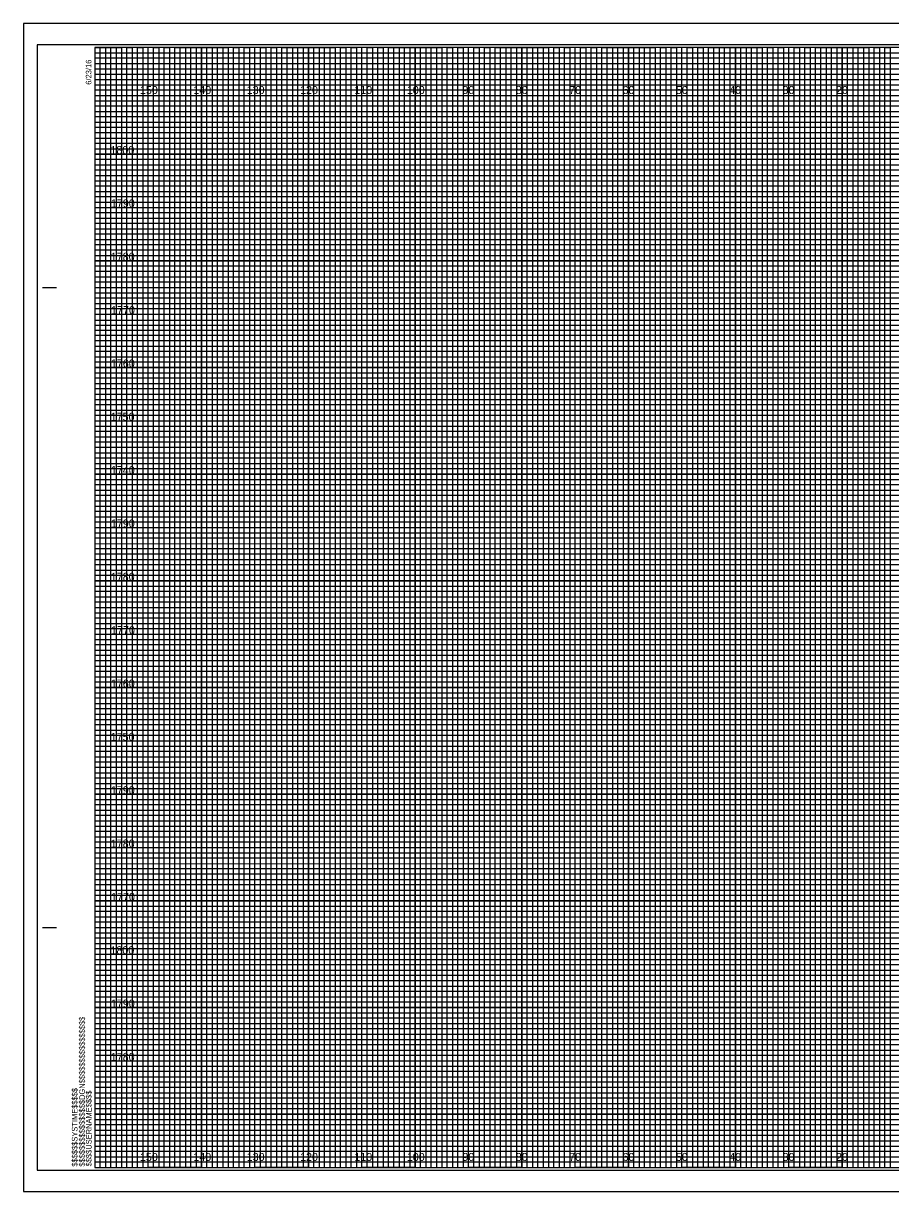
# Model space of a CAD drawing. Extents: x -163 to 174, y 11 to 1110.
# Drawn here: x -162.9 to -0.4, y 451.2 to 670.2 of the extents above; entities that cross this region are included whole.
import ezdxf

# ---------------------------------------------------------------- set-up
doc = ezdxf.new("R2010")
doc.units = 0
for name, color, linetype in [('Prop XS DDE', 7, 'Continuous'), ('Prop XS Earthwork Shape', 7, 'Continuous'), ('Prop XS Elevation Labels', 7, 'Continuous'), ('Sheet Cross Section CELL', 7, 'Continuous'), ('Sheet Cross Section Grid Middle CELL', 7, 'Continuous'), ('Sheet Cross Section Grid Minor 1 CELL', 7, 'Continuous'), ('Sheet Cross Section Grid Minor 2 CELL', 7, 'Continuous'), ('Sheet Cutting Line CELL', 7, 'Continuous'), ('Sheet DOT Grid CELL', 7, 'Continuous'), ('Sheet Plot Border Inside CELL', 7, 'Continuous'), ('Sheet Plot Border Outside CELL', 7, 'Continuous')]:
    doc.layers.add(name, color=color, linetype=linetype)

msp = doc.modelspace()

# ---------------------------------------------------------------- linework, layer by layer
at = {"layer": 'Prop XS DDE'}
for p, q in [((-139.53, 665.7), (-149.53, 665.7)), ((-139.53, 455.7), (-139.53, 665.7)), ((-119.53, 665.7), (-129.53, 665.7)), ((-129.53, 665.7), (-129.53, 455.7)), ((-119.53, 455.7), (-119.53, 665.7)), ((-99.53, 665.7), (-109.53, 665.7)), ((-109.53, 665.7), (-109.53, 455.7)), ((-99.53, 455.7), (-99.53, 665.7)), ((-79.53, 665.7), (-89.53, 665.7)), ((-89.53, 665.7), (-89.53, 455.7)), ((-79.53, 455.7), (-79.53, 665.7)), ((-59.53, 665.7), (-69.53, 665.7)), ((-69.53, 665.7), (-69.53, 455.7)), ((-59.53, 455.7), (-59.53, 665.7)), ((-39.53, 665.7), (-49.53, 665.7)), ((-49.53, 665.7), (-49.53, 455.7)), ((-39.53, 455.7), (-39.53, 665.7)), ((-19.53, 665.7), (-29.53, 665.7)), ((-29.53, 665.7), (-29.53, 455.7)), ((-19.53, 455.7), (-19.53, 665.7)), ((0.47, 665.7), (-9.53, 665.7)), ((-9.53, 665.7), (-9.53, 455.7)), ((-129.53, 455.7), (-139.53, 455.7)), ((-109.53, 455.7), (-119.53, 455.7)), ((-89.53, 455.7), (-99.53, 455.7)), ((-69.53, 455.7), (-79.53, 455.7)), ((-49.53, 455.7), (-59.53, 455.7)), ((-29.53, 455.7), (-39.53, 455.7)), ((-9.53, 455.7), (-19.53, 455.7))]:
    msp.add_line(p, q, dxfattribs=at)
for points in [[(-149.53, 655.7), (170.47, 655.7), (170.47, 645.7), (-149.53, 645.7)], [(-149.53, 635.7), (170.47, 635.7), (170.47, 625.7), (-149.53, 625.7)], [(-149.53, 615.7), (170.47, 615.7), (170.47, 605.7), (-149.53, 605.7)], [(-149.53, 595.7), (170.47, 595.7), (170.47, 585.7), (-149.53, 585.7)], [(-149.53, 575.7), (170.47, 575.7), (170.47, 565.7), (-149.53, 565.7)], [(-149.53, 555.7), (170.47, 555.7), (170.47, 545.7), (-149.53, 545.7)], [(-149.53, 535.7), (170.47, 535.7), (170.47, 525.7), (-149.53, 525.7)], [(-149.53, 515.7), (170.47, 515.7), (170.47, 505.7), (-149.53, 505.7)], [(-149.53, 495.7), (170.47, 495.7), (170.47, 485.7), (-149.53, 485.7)], [(-149.53, 475.7), (170.47, 475.7), (170.47, 465.7), (-149.53, 465.7)]]:
    msp.add_lwpolyline(points, dxfattribs=at)
at = {"layer": 'Sheet Cross Section CELL'}
for p, q in [((-159.33, 620.7), (-156.83, 620.7)), ((-159.23, 620.7), (-156.73, 620.7)), ((-159.33, 500.7), (-156.83, 500.7)), ((-159.23, 500.7), (-156.73, 500.7)), ((-149.53, 455.7), (-149.53, 455.7)), ((-149.53, 455.7), (-149.53, 455.7)), ((-149.53, 455.7), (-149.53, 455.7)), ((-149.53, 455.7), (-149.53, 455.7)), ((-149.53, 455.7), (-149.53, 455.7)), ((-149.53, 455.7), (-149.53, 455.7)), ((-149.53, 455.7), (-149.53, 455.7))]:
    msp.add_line(p, q, dxfattribs=at)
msp.add_lwpolyline([(170.47, 665.7), (-149.53, 665.7), (-149.53, 455.7), (170.47, 455.7)], close=True, dxfattribs=at)
at = {"layer": 'Sheet Cross Section Grid Middle CELL'}
for points in [[(-149.53, 665.7), (-144.53, 665.7), (-144.53, 455.7), (-134.53, 455.7), (-134.53, 665.7), (-124.53, 665.7), (-124.53, 455.7), (-114.53, 455.7), (-114.53, 665.7), (-104.53, 665.7), (-104.53, 455.7), (-94.53, 455.7), (-94.53, 665.7), (-84.53, 665.7), (-84.53, 455.7), (-74.53, 455.7), (-74.53, 665.7), (-64.53, 665.7), (-64.53, 455.7), (-54.53, 455.7), (-54.53, 665.7), (-44.53, 665.7), (-44.53, 455.7), (-34.53, 455.7), (-34.53, 665.7), (-24.53, 665.7), (-24.53, 455.7), (-14.53, 455.7), (-14.53, 665.7), (-4.53, 665.7), (-4.53, 455.7), (5.47, 455.7)], [(-149.53, 660.7), (125.47, 660.7)], [(-149.53, 640.7), (170.47, 640.7), (170.47, 650.7), (-149.53, 650.7)], [(-149.53, 620.7), (170.47, 620.7), (170.47, 630.7), (-149.53, 630.7)], [(-149.53, 600.7), (170.47, 600.7), (170.47, 610.7), (-149.53, 610.7)], [(-149.53, 580.7), (170.47, 580.7), (170.47, 590.7), (-149.53, 590.7)], [(-149.53, 560.7), (170.47, 560.7), (170.47, 570.7), (-149.53, 570.7)], [(-149.53, 540.7), (170.47, 540.7), (170.47, 550.7), (-149.53, 550.7)], [(-149.53, 520.7), (170.47, 520.7), (170.47, 530.7), (-149.53, 530.7)], [(-149.53, 500.7), (170.47, 500.7), (170.47, 510.7), (-149.53, 510.7)], [(-149.53, 480.7), (170.47, 480.7), (170.47, 490.7), (-149.53, 490.7)], [(-149.53, 460.7), (170.47, 460.7), (170.47, 470.7), (-149.53, 470.7)]]:
    msp.add_lwpolyline(points, dxfattribs=at)
at = {"layer": 'Sheet Cross Section Grid Minor 1 CELL'}
for p, q in [((-149.53, 664.7), (110.47, 664.7)), ((110.47, 663.68), (-149.53, 663.68)), ((-149.53, 663.68), (-149.53, 662.7)), ((-149.53, 662.7), (110.47, 662.7)), ((110.47, 661.59), (-149.53, 661.59)), ((-149.53, 661.59), (-149.53, 659.7)), ((-149.53, 659.7), (170.47, 659.7))]:
    msp.add_line(p, q, dxfattribs=at)
for points in [[(-149.53, 658.7), (120.47, 658.7), (170.47, 658.7), (170.47, 657.7), (-149.53, 657.7)], [(-149.53, 656.7), (170.47, 656.7), (170.47, 654.7), (-149.53, 654.7)], [(-149.53, 653.7), (170.47, 653.7), (170.47, 652.7), (-149.53, 652.68)], [(-149.53, 651.7), (170.47, 651.7), (170.47, 649.7), (-149.53, 649.7)], [(-149.53, 648.7), (170.47, 648.7), (170.47, 647.7), (-149.53, 647.7)], [(-149.53, 646.7), (170.47, 646.7), (170.47, 644.7), (-149.53, 644.7)], [(-149.53, 643.7), (170.47, 643.7), (170.47, 642.7), (-149.53, 642.7)], [(-149.53, 641.7), (170.47, 641.7), (170.47, 639.7), (-149.53, 639.7)], [(-149.53, 638.7), (170.47, 638.7), (170.47, 637.7), (-149.53, 637.7)], [(-149.53, 636.7), (170.47, 636.7), (170.47, 634.7), (-149.53, 634.7)], [(-149.53, 633.7), (170.47, 633.7), (170.47, 632.7), (-149.53, 632.7)], [(-149.53, 631.7), (170.47, 631.7), (170.47, 629.65), (170.47, 628.7), (170.47, 627.7), (-149.53, 627.7)], [(-149.53, 629.7), (170.47, 629.7), (170.47, 628.7), (-149.53, 628.7)], [(-149.53, 626.7), (170.47, 626.7), (170.47, 624.7), (-149.53, 624.73)], [(-149.53, 624.73), (170.47, 624.7), (170.47, 623.7), (-149.53, 623.7)], [(-149.53, 622.7), (170.47, 622.7), (170.47, 621.7), (-149.53, 621.7)], [(-149.53, 619.7), (170.47, 619.7), (170.47, 618.7), (-149.53, 618.7)], [(-149.53, 617.7), (170.47, 617.7), (170.47, 616.7), (-149.53, 616.7)], [(-149.6, 614.59), (170.47, 614.59), (170.47, 613.58), (-149.6, 613.58)], [(-149.53, 612.7), (170.47, 612.7), (170.47, 611.7), (-149.53, 611.7)], [(-149.53, 609.7), (170.47, 609.7), (170.47, 608.7), (-149.53, 608.7)], [(-149.53, 607.7), (170.47, 607.7), (170.47, 606.7), (-149.53, 606.7)], [(-149.53, 604.7), (170.47, 604.7), (170.47, 603.7), (-149.53, 603.7)], [(-149.53, 602.7), (170.47, 602.7), (170.47, 601.7), (-149.53, 601.7)], [(-149.53, 599.7), (170.47, 599.7), (170.47, 598.7), (-149.53, 598.7)], [(-149.53, 597.7), (170.47, 597.7), (170.47, 596.7), (-149.53, 596.7)], [(-149.53, 594.7), (170.47, 594.7), (170.46, 593.68), (-149.53, 593.7)], [(-149.53, 592.7), (170.47, 592.7), (170.47, 591.7), (-149.53, 591.7)], [(-149.53, 589.7), (170.47, 589.7), (170.47, 588.7), (-149.53, 588.7)], [(-149.53, 587.7), (170.47, 587.7), (170.47, 586.7), (-149.53, 586.7)], [(-149.53, 584.7), (170.47, 584.7), (170.47, 583.7), (-149.53, 583.7)], [(-149.53, 582.7), (170.47, 582.7), (170.47, 581.7), (-149.53, 581.7)], [(-149.53, 579.7), (170.47, 579.7), (170.47, 578.7), (-149.53, 578.7)], [(-149.53, 577.7), (170.47, 577.7), (170.47, 576.7), (-149.53, 576.7)], [(-149.53, 574.7), (170.47, 574.7), (170.47, 573.7), (-149.53, 573.7)], [(-149.53, 572.69), (170.54, 572.61), (170.47, 571.7), (-149.53, 571.7)], [(-149.53, 569.7), (170.47, 569.7), (170.47, 568.7), (-149.53, 568.7)], [(-149.53, 567.7), (170.47, 567.7), (170.47, 566.7), (-149.53, 566.7)], [(-149.53, 564.7), (170.47, 564.7), (170.47, 563.7), (-149.53, 563.7)], [(-149.53, 562.7), (170.47, 562.7), (170.47, 561.7), (-149.53, 561.7)], [(-149.53, 559.7), (170.47, 559.7), (170.47, 558.7), (-149.53, 558.7)], [(-149.53, 557.7), (170.47, 557.7), (170.47, 556.7), (-149.53, 556.7)], [(-149.53, 554.7), (170.47, 554.7), (170.47, 553.7), (-149.53, 553.7)], [(-149.53, 552.7), (170.47, 552.7), (170.47, 551.7), (-149.53, 551.7)], [(-149.53, 549.7), (170.47, 549.7), (170.47, 548.7), (-149.53, 548.7)], [(-149.53, 547.7), (170.47, 547.7), (170.47, 546.7), (-149.53, 546.7)], [(-149.53, 544.7), (170.47, 544.7), (170.47, 543.7), (-149.53, 543.7)], [(-149.53, 542.7), (170.47, 542.7), (170.47, 541.7), (-149.53, 541.7)], [(-149.53, 539.7), (170.47, 539.7), (170.47, 538.7), (-149.53, 538.7)], [(-149.53, 537.7), (170.47, 537.7), (170.47, 536.7), (-149.53, 536.7)], [(-149.53, 534.7), (170.47, 534.7), (170.46, 533.68), (-149.53, 533.7)], [(-149.53, 532.7), (170.47, 532.7), (170.47, 531.7), (-149.53, 531.7)], [(-149.53, 529.7), (170.47, 529.7), (170.47, 528.7), (-149.53, 528.7)], [(-149.53, 527.7), (170.47, 527.7), (170.47, 526.7), (-149.53, 526.7)], [(-149.53, 524.7), (170.47, 524.7), (170.47, 523.7), (-149.53, 523.7)], [(-149.53, 522.7), (170.47, 522.7), (170.47, 521.7), (-149.53, 521.7)], [(-149.53, 519.7), (170.47, 519.7), (170.47, 518.7), (-149.53, 518.7)], [(-149.53, 517.7), (170.47, 517.7), (170.47, 516.7), (-149.53, 516.7)], [(-149.53, 514.7), (170.47, 514.7), (170.47, 513.7), (-149.53, 513.7)], [(-149.53, 512.69), (170.54, 512.61), (170.47, 511.7), (-149.53, 511.7)], [(-149.53, 509.7), (170.47, 509.7), (170.47, 508.7), (-149.53, 508.7)], [(-149.53, 507.7), (170.47, 507.7), (170.47, 506.7), (-149.53, 506.7)], [(-149.53, 504.7), (170.47, 504.7), (170.47, 503.7), (-149.53, 503.7)], [(-149.53, 502.7), (170.47, 502.7), (170.47, 501.7), (-149.53, 501.7)], [(-149.53, 499.7), (170.47, 499.7), (170.47, 498.7), (-149.53, 498.7)], [(-149.53, 497.7), (170.47, 497.7), (170.47, 496.7), (-149.53, 496.7)], [(-149.53, 494.7), (170.47, 494.7), (170.47, 493.7), (-149.53, 493.7)], [(-149.53, 492.7), (170.47, 492.7), (170.47, 491.7), (-149.53, 491.7)], [(-149.53, 489.7), (170.47, 489.7), (170.47, 488.7), (-149.53, 488.7)], [(-149.53, 487.7), (170.47, 487.7), (170.47, 486.7), (-149.53, 486.7)], [(-149.53, 484.7), (170.47, 484.7), (170.47, 483.7), (-149.53, 483.7)], [(-149.53, 482.7), (170.47, 482.7), (170.47, 481.7), (-149.53, 481.7)], [(-149.53, 479.7), (170.47, 479.7), (170.47, 478.7), (-149.53, 478.7)], [(-149.53, 477.7), (170.47, 477.7), (170.47, 476.7), (-149.53, 476.7)], [(-149.53, 474.7), (170.47, 474.7), (170.47, 473.7), (-149.53, 473.7)], [(-149.53, 472.7), (170.47, 472.7), (170.47, 471.7), (-149.53, 471.7)], [(-149.53, 469.7), (170.47, 469.7), (170.47, 468.7), (-149.53, 468.7)], [(-149.53, 467.7), (170.47, 467.7), (170.47, 466.7), (-149.53, 466.7)], [(-149.53, 464.7), (170.47, 464.7), (170.47, 463.7), (-149.53, 463.7)], [(-149.53, 462.7), (170.47, 462.7), (170.47, 461.7), (-149.53, 461.7)], [(-149.53, 459.7), (170.47, 459.7), (170.47, 458.7), (-149.53, 458.7)], [(-149.53, 457.7), (170.47, 457.7), (170.47, 456.7), (-149.53, 456.7)]]:
    msp.add_lwpolyline(points, dxfattribs=at)
at = {"layer": 'Sheet Cross Section Grid Minor 2 CELL'}
for points in [[(-149.53, 455.7), (-148.53, 455.7), (-148.53, 665.7), (-147.53, 665.7), (-147.53, 455.7)], [(-147.53, 455.7), (-146.53, 455.7), (-146.53, 665.7), (-145.53, 665.7), (-145.53, 455.7)], [(-144.53, 455.7), (-143.53, 455.7), (-143.53, 665.7), (-142.53, 665.7), (-142.53, 455.7)], [(-142.53, 455.7), (-141.53, 455.7), (-141.53, 665.7), (-140.53, 665.7), (-140.53, 455.7)], [(-139.53, 455.7), (-138.53, 455.7), (-138.53, 665.7), (-137.53, 665.7), (-137.53, 455.7)], [(-137.53, 455.7), (-136.53, 455.7), (-136.53, 665.7), (-135.53, 665.7), (-135.53, 455.7)], [(-134.53, 455.7), (-133.53, 455.7), (-133.53, 665.7), (-132.53, 665.7), (-132.53, 455.7)], [(-132.53, 455.7), (-131.53, 455.7), (-131.53, 665.7), (-130.53, 665.7), (-130.53, 455.7)], [(-129.53, 455.7), (-128.53, 455.7), (-128.53, 665.7), (-127.53, 665.7), (-127.53, 455.7)], [(-127.53, 455.7), (-126.53, 455.7), (-126.53, 665.7), (-125.53, 665.7), (-125.53, 455.7)], [(-124.53, 455.7), (-123.53, 455.7), (-123.53, 665.7), (-122.53, 665.7), (-122.53, 455.7)], [(-122.53, 455.7), (-121.53, 455.7), (-121.53, 665.7), (-120.53, 665.7), (-120.53, 455.7)], [(-119.53, 455.7), (-118.53, 455.7), (-118.53, 665.7), (-117.53, 665.7), (-117.53, 455.7)], [(-117.53, 455.7), (-116.53, 455.7), (-116.53, 665.7), (-115.53, 665.7), (-115.53, 455.7)], [(-114.53, 455.7), (-113.53, 455.7), (-113.53, 665.7), (-112.53, 665.7), (-112.53, 455.7)], [(-112.53, 455.7), (-111.53, 455.7), (-111.53, 665.7), (-110.53, 665.7), (-110.53, 455.7)], [(-109.53, 455.7), (-108.53, 455.7), (-108.53, 665.7), (-107.53, 665.7), (-107.53, 455.7)], [(-107.53, 455.7), (-106.53, 455.7), (-106.53, 665.7), (-105.53, 665.7), (-105.53, 455.7)], [(-104.53, 455.7), (-103.53, 455.7), (-103.53, 665.7), (-102.53, 665.7), (-102.53, 455.7)], [(-102.53, 455.7), (-101.53, 455.7), (-101.53, 665.7), (-100.53, 665.7), (-100.53, 455.7)], [(-99.53, 455.7), (-98.53, 455.7), (-98.53, 665.7), (-97.53, 665.7), (-97.53, 455.7)], [(-97.53, 455.7), (-96.53, 455.7), (-96.53, 665.7), (-95.53, 665.7), (-95.53, 455.7)], [(-94.53, 455.7), (-93.53, 455.7), (-93.53, 665.7), (-92.53, 665.7), (-92.53, 455.7)], [(-92.53, 455.7), (-91.53, 455.7), (-91.53, 665.7), (-90.53, 665.7), (-90.53, 455.7)], [(-89.53, 455.7), (-88.53, 455.7), (-88.53, 665.7), (-87.53, 665.7), (-87.53, 455.7)], [(-87.53, 455.7), (-86.53, 455.7), (-86.53, 665.7), (-85.53, 665.7), (-85.53, 455.7)], [(-84.53, 455.7), (-83.53, 455.7), (-83.53, 665.7), (-82.53, 665.7), (-82.53, 455.7)], [(-82.53, 455.7), (-81.53, 455.7), (-81.53, 665.7), (-80.53, 665.7), (-80.53, 455.7)], [(-79.53, 455.7), (-78.53, 455.7), (-78.53, 665.7), (-77.53, 665.7), (-77.53, 455.7)], [(-77.53, 455.7), (-76.53, 455.7), (-76.53, 665.7), (-75.53, 665.7), (-75.53, 455.7)], [(-74.53, 455.7), (-73.53, 455.7), (-73.53, 665.7), (-72.53, 665.7), (-72.53, 455.7)], [(-72.53, 455.7), (-71.53, 455.7), (-71.53, 665.7), (-70.53, 665.7), (-70.53, 455.7)], [(-69.53, 455.7), (-68.53, 455.7), (-68.53, 665.7), (-67.53, 665.7), (-67.53, 455.7)], [(-67.53, 455.7), (-66.53, 455.7), (-66.53, 665.7), (-65.53, 665.7), (-65.53, 455.7)], [(-64.53, 455.7), (-63.53, 455.7), (-63.53, 665.7), (-62.53, 665.7), (-62.53, 455.7)], [(-62.53, 455.7), (-61.53, 455.7), (-61.53, 665.7), (-60.53, 665.7), (-60.53, 455.7)], [(-59.53, 455.7), (-58.53, 455.7), (-58.53, 665.7), (-57.53, 665.7), (-57.53, 455.7)], [(-57.53, 455.7), (-56.53, 455.7), (-56.53, 665.7), (-55.53, 665.7), (-55.53, 455.7)], [(-54.53, 455.7), (-53.53, 455.7), (-53.53, 665.7), (-52.53, 665.7), (-52.53, 455.7)], [(-52.53, 455.7), (-51.53, 455.7), (-51.53, 665.7), (-50.53, 665.7), (-50.53, 455.7)], [(-49.53, 455.7), (-48.53, 455.7), (-48.53, 665.7), (-47.53, 665.7), (-47.53, 455.7)], [(-47.53, 455.7), (-46.53, 455.7), (-46.53, 665.7), (-45.53, 665.7), (-45.53, 455.7)], [(-44.53, 455.7), (-43.53, 455.7), (-43.53, 665.7), (-42.53, 665.7), (-42.53, 455.7)], [(-42.53, 455.7), (-41.53, 455.7), (-41.53, 665.7), (-40.53, 665.7), (-40.53, 455.7)], [(-39.53, 455.7), (-38.53, 455.7), (-38.53, 665.7), (-37.53, 665.7), (-37.53, 455.7)], [(-37.53, 455.7), (-36.53, 455.7), (-36.53, 665.7), (-35.53, 665.7), (-35.53, 455.7)], [(-34.53, 455.7), (-33.53, 455.7), (-33.53, 665.7), (-32.53, 665.7), (-32.53, 455.7)], [(-32.53, 455.7), (-31.53, 455.7), (-31.53, 665.7), (-30.53, 665.7), (-30.53, 455.7)], [(-29.53, 455.7), (-28.53, 455.7), (-28.53, 665.7), (-27.53, 665.7), (-27.53, 455.7)], [(-27.53, 455.7), (-26.53, 455.7), (-26.53, 665.7), (-25.53, 665.7), (-25.53, 455.7)], [(-24.53, 455.7), (-23.53, 455.7), (-23.53, 665.7), (-22.53, 665.7), (-22.53, 455.7)], [(-22.53, 455.7), (-21.53, 455.7), (-21.53, 665.7), (-20.53, 665.7), (-20.53, 455.7)], [(-19.53, 455.7), (-18.53, 455.7), (-18.53, 665.7), (-17.53, 665.7), (-17.53, 455.7)], [(-17.53, 455.7), (-16.53, 455.7), (-16.53, 665.7), (-15.53, 665.7), (-15.53, 455.7)], [(-14.53, 455.7), (-13.53, 455.7), (-13.53, 665.7), (-12.53, 665.7), (-12.53, 455.7)], [(-12.53, 455.7), (-11.53, 455.7), (-11.53, 665.7), (-10.53, 665.7), (-10.53, 455.7)], [(-9.53, 455.7), (-8.53, 455.7), (-8.53, 665.7), (-7.53, 665.7), (-7.53, 455.7)], [(-7.53, 455.7), (-6.53, 455.7), (-6.53, 665.7), (-5.53, 665.7), (-5.53, 455.7)], [(-4.53, 455.7), (-3.53, 455.7), (-3.53, 665.7), (-2.53, 665.7), (-2.53, 455.7)], [(-2.53, 455.7), (-1.53, 455.7), (-1.53, 665.7), (-0.53, 665.7), (-0.53, 455.7)]]:
    msp.add_lwpolyline(points, dxfattribs=at)
at = {"layer": 'Sheet Cutting Line CELL'}
for p, q in [((173.77, 670.2), (-162.93, 670.2)), ((-162.93, 670.2), (-162.93, 451.2)), ((-162.93, 451.2), (173.77, 451.2))]:
    msp.add_line(p, q, dxfattribs=at)
at = {"layer": 'Sheet DOT Grid CELL'}
for p, q in [((-139.53, 455.7), (-139.53, 665.7)), ((-129.53, 455.7), (-129.53, 665.7)), ((-119.53, 455.7), (-119.53, 665.7)), ((-109.53, 455.7), (-109.53, 665.7)), ((-99.53, 455.7), (-99.53, 665.7)), ((-89.53, 455.7), (-89.53, 665.7)), ((-79.53, 455.7), (-79.53, 665.7)), ((-69.53, 455.7), (-69.53, 665.7)), ((-59.53, 455.7), (-59.53, 665.7)), ((-49.53, 455.7), (-49.53, 665.7)), ((-39.53, 455.7), (-39.53, 665.7)), ((-29.53, 455.7), (-29.53, 665.7)), ((-19.53, 455.7), (-19.53, 665.7)), ((-9.53, 455.7), (-9.53, 665.7)), ((-149.53, 655.7), (170.47, 655.7)), ((-149.53, 645.7), (170.47, 645.7)), ((-149.53, 635.7), (170.47, 635.7)), ((-149.53, 625.7), (170.47, 625.7)), ((-149.53, 615.7), (170.47, 615.7)), ((-149.53, 605.7), (170.47, 605.7)), ((-149.53, 595.7), (170.47, 595.7)), ((-149.53, 585.7), (170.47, 585.7)), ((-149.53, 575.7), (170.47, 575.7)), ((-149.53, 565.7), (170.47, 565.7)), ((-149.53, 555.7), (170.47, 555.7)), ((-149.53, 545.7), (170.47, 545.7)), ((-149.53, 535.7), (170.47, 535.7)), ((-149.53, 525.7), (170.47, 525.7)), ((-149.53, 515.7), (170.47, 515.7)), ((-149.53, 505.7), (170.47, 505.7)), ((-149.53, 495.7), (170.47, 495.7)), ((-149.53, 485.7), (170.47, 485.7)), ((-149.53, 475.7), (170.47, 475.7)), ((-149.53, 465.7), (170.47, 465.7))]:
    msp.add_line(p, q, dxfattribs=at)
at = {"layer": 'Sheet Plot Border Inside CELL'}
msp.add_lwpolyline([(-160.33, 455.2), (172.87, 455.2), (172.87, 666.2), (-160.33, 666.2)], close=True, dxfattribs=at)
at = {"layer": 'Sheet Plot Border Outside CELL'}
msp.add_lwpolyline([(-162.93, 451.2), (173.77, 451.2), (173.77, 670.2), (-162.93, 670.2)], close=True, dxfattribs=at)

# ---------------------------------------------------------------- texts
at = {"layer": 'Prop XS Earthwork Shape'}
for s, p in [('150', (-141.08, 656.95)), ('140', (-131.08, 656.95)), ('130', (-121.08, 656.95)), ('120', (-111.08, 656.95)), ('110', (-100.91, 656.95)), ('100', (-91.08, 656.95)), ('90', (-80.67, 656.95)), ('80', (-70.67, 656.95)), ('70', (-60.67, 656.95)), ('60', (-50.67, 656.95)), ('50', (-40.67, 656.95)), ('40', (-30.67, 656.95)), ('30', (-20.67, 656.95)), ('20', (-10.67, 656.95)), ('150', (-141.08, 456.95)), ('140', (-131.08, 456.95)), ('130', (-121.08, 456.95)), ('120', (-111.08, 456.95)), ('110', (-100.91, 456.95)), ('100', (-91.08, 456.95)), ('90', (-80.67, 456.95)), ('80', (-70.67, 456.95)), ('70', (-60.67, 456.95)), ('60', (-50.67, 456.95)), ('50', (-40.67, 456.95)), ('40', (-30.67, 456.95)), ('30', (-20.67, 456.95)), ('20', (-10.67, 456.95))]:
    msp.add_text(s, height=1.5, dxfattribs=at).set_placement(p)
at = {"layer": 'Prop XS Elevation Labels'}
for s, p in [('1800', (-146.61, 645.7)), ('1790', (-146.53, 635.7)), ('1780', (-146.55, 625.7)), ('1770', (-146.49, 615.7)), ('1760', (-146.53, 605.7)), ('1750', (-146.57, 595.7)), ('1740', (-146.53, 585.7)), ('1790', (-146.53, 575.7)), ('1780', (-146.55, 565.7)), ('1770', (-146.49, 555.7)), ('1760', (-146.53, 545.7)), ('1750', (-146.57, 535.7)), ('1790', (-146.53, 525.7)), ('1780', (-146.55, 515.7)), ('1770', (-146.49, 505.7)), ('1800', (-146.61, 495.7)), ('1790', (-146.53, 485.7)), ('1780', (-146.55, 475.7))]:
    msp.add_text(s, height=1.5, dxfattribs=at).set_placement(p)
at = {"layer": 'Sheet Cross Section CELL'}
for s, p in [('6/23/16', (-150.18, 658.7)), ('$$$$$$$$$$$$$$$$DGN$$$$$$$$$$$$$$$$', (-151.41, 455.88)), ('$$$$$$SYSTIME$$$$$', (-152.79, 455.88)), ('$$$$USERNAME$$$$', (-150.15, 455.93))]:
    msp.add_text(s, height=1.05, rotation=90, dxfattribs=at).set_placement(p)

doc.saveas('drawing.dxf')
